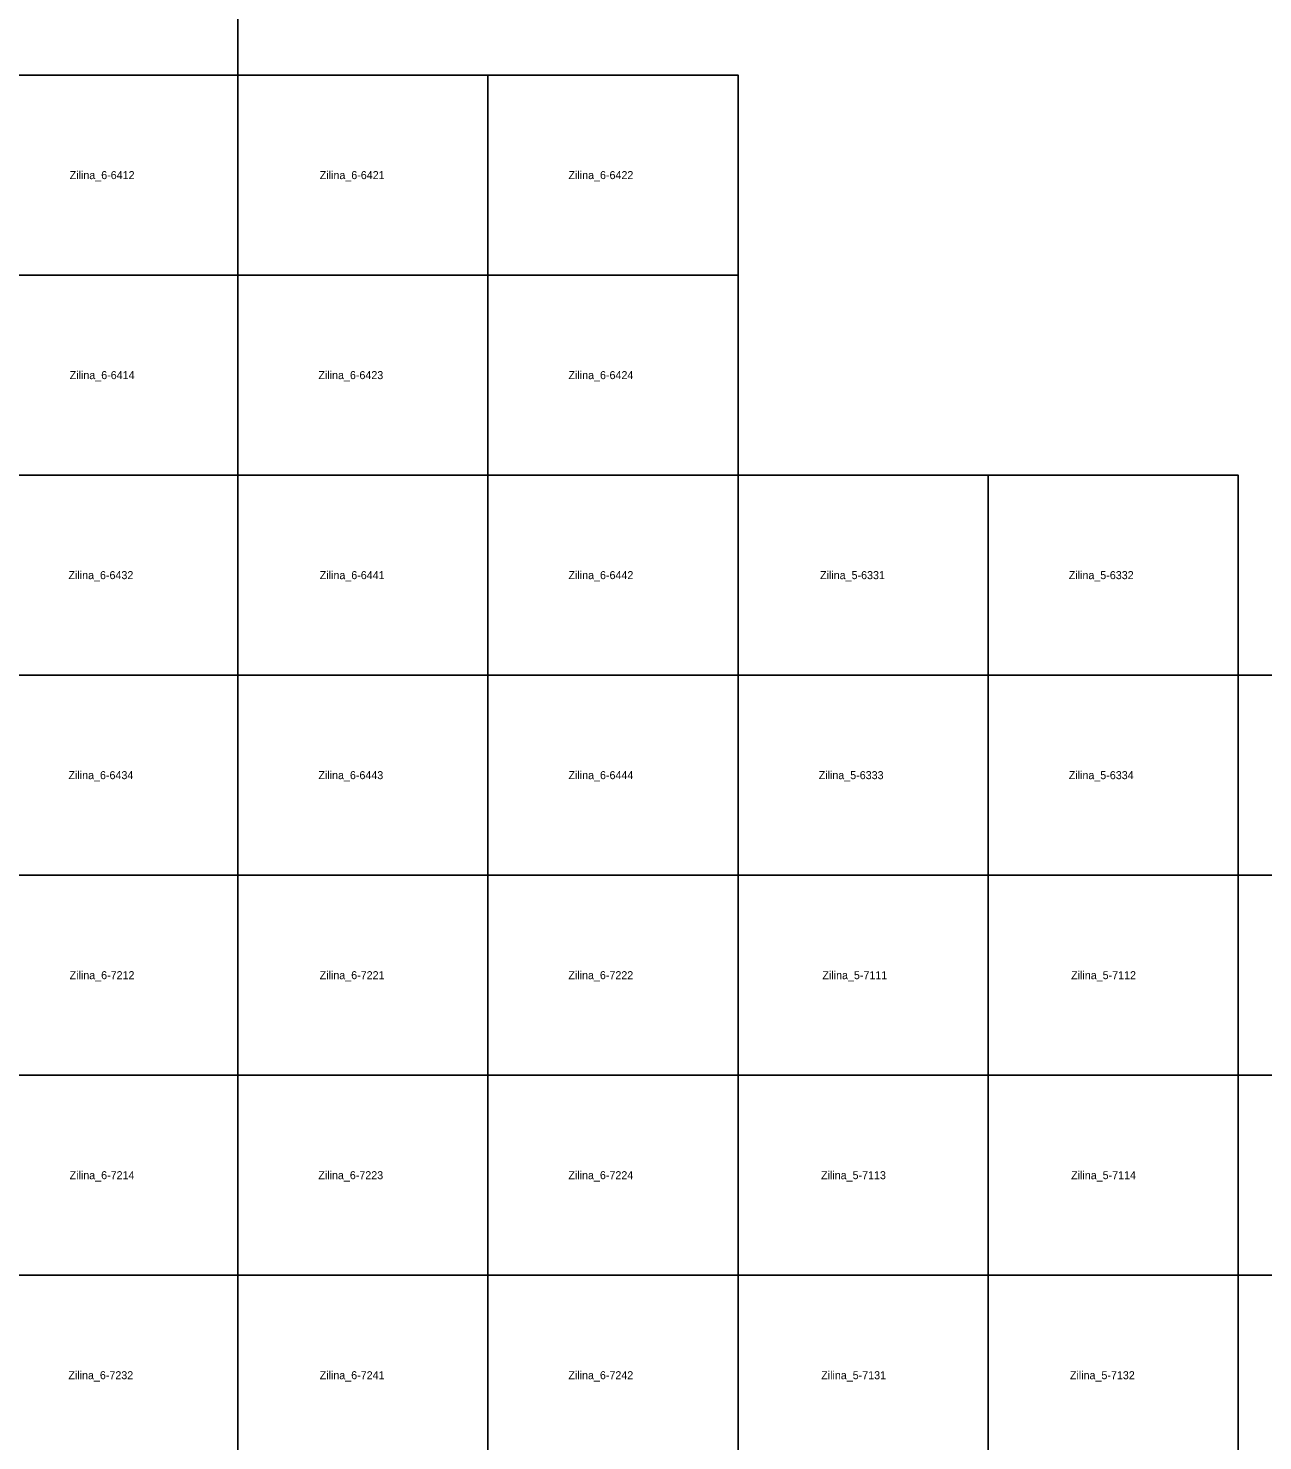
# Model space of a CAD drawing. Extents: x -445938 to -437812, y -1177250 to -1169500.
# Drawn here: x -440887 to -439344, y -1174707 to -1172941 of the extents above; entities that cross this region are included whole.
import ezdxf

# ---------------------------------------------------------------- set-up
doc = ezdxf.new("R2010")
doc.units = 0
for name, color, linetype in [('Vrstva 1', 7, 'Continuous'), ('Vrstva 4', 7, 'Continuous'), ('Vrstva 6', 7, 'Continuous')]:
    doc.layers.add(name, color=color, linetype=linetype)

msp = doc.modelspace()

# ---------------------------------------------------------------- linework, layer by layer
at = {"layer": 'Vrstva 1'}
msp.add_lwpolyline([(-440937.5, -1172000), (-440625, -1172000), (-440625, -1173000), (-440000, -1173000), (-440000, -1173500), (-439375, -1173500), (-439375, -1173750), (-438750, -1173750), (-438750, -1174000), (-438125, -1174000), (-438125, -1174750), (-437812.5, -1174750), (-437812.5, -1176750), (-438125, -1176750), (-438125, -1177000), (-438437.5, -1177000), (-438437.5, -1177250), (-439687.5, -1177250), (-439687.5, -1176750), (-440625, -1176750), (-440625, -1175500), (-441562.5, -1175500)], dxfattribs=at)
at = {"layer": 'Vrstva 4'}
for points in [[(-440625, -1172750), (-440625, -1173000), (-440937.5, -1173000), (-440937.5, -1172750)], [(-440625, -1173000), (-440625, -1173250), (-440937.5, -1173250), (-440937.5, -1173000)], [(-440312.5, -1173000), (-440312.5, -1173250), (-440625, -1173250), (-440625, -1173000)], [(-440000, -1173000), (-440000, -1173250), (-440312.5, -1173250), (-440312.5, -1173000)], [(-440625, -1173250), (-440625, -1173500), (-440937.5, -1173500), (-440937.5, -1173250)], [(-440312.5, -1173250), (-440312.5, -1173500), (-440625, -1173500), (-440625, -1173250)], [(-440000, -1173250), (-440000, -1173500), (-440312.5, -1173500), (-440312.5, -1173250)], [(-440625, -1173500), (-440625, -1173750), (-440937.5, -1173750), (-440937.5, -1173500)], [(-440312.5, -1173500), (-440312.5, -1173750), (-440625, -1173750), (-440625, -1173500)], [(-440000, -1173500), (-440000, -1173750), (-440312.5, -1173750), (-440312.5, -1173500)], [(-439687.5, -1173500), (-439687.5, -1173750), (-440000, -1173750), (-440000, -1173500)], [(-439375, -1173500), (-439375, -1173750), (-439687.5, -1173750), (-439687.5, -1173500)], [(-440625, -1173750), (-440625, -1174000), (-440937.5, -1174000), (-440937.5, -1173750)], [(-440312.5, -1173750), (-440312.5, -1174000), (-440625, -1174000), (-440625, -1173750)], [(-440000, -1173750), (-440000, -1174000), (-440312.5, -1174000), (-440312.5, -1173750)], [(-439687.5, -1173750), (-439687.5, -1174000), (-440000, -1174000), (-440000, -1173750)], [(-439375, -1173750), (-439375, -1174000), (-439687.5, -1174000), (-439687.5, -1173750)], [(-439062.5, -1173750), (-439062.5, -1174000), (-439375, -1174000), (-439375, -1173750)], [(-440625, -1174000), (-440625, -1174250), (-440937.5, -1174250), (-440937.5, -1174000)], [(-440312.5, -1174000), (-440312.5, -1174250), (-440625, -1174250), (-440625, -1174000)], [(-440000, -1174000), (-440000, -1174250), (-440312.5, -1174250), (-440312.5, -1174000)], [(-439687.5, -1174000), (-439687.5, -1174250), (-440000, -1174250), (-440000, -1174000)], [(-439375, -1174000), (-439375, -1174250), (-439687.5, -1174250), (-439687.5, -1174000)], [(-439062.5, -1174000), (-439062.5, -1174250), (-439375, -1174250), (-439375, -1174000)], [(-440625, -1174250), (-440625, -1174500), (-440937.5, -1174500), (-440937.5, -1174250)], [(-440312.5, -1174250), (-440312.5, -1174500), (-440625, -1174500), (-440625, -1174250)], [(-440000, -1174250), (-440000, -1174500), (-440312.5, -1174500), (-440312.5, -1174250)], [(-439687.5, -1174250), (-439687.5, -1174500), (-440000, -1174500), (-440000, -1174250)], [(-439375, -1174250), (-439375, -1174500), (-439687.5, -1174500), (-439687.5, -1174250)], [(-439062.5, -1174250), (-439062.5, -1174500), (-439375, -1174500), (-439375, -1174250)], [(-440625, -1174500), (-440625, -1174750), (-440937.5, -1174750), (-440937.5, -1174500)], [(-440312.5, -1174500), (-440312.5, -1174750), (-440625, -1174750), (-440625, -1174500)], [(-440000, -1174500), (-440000, -1174750), (-440312.5, -1174750), (-440312.5, -1174500)], [(-439687.5, -1174500), (-439687.5, -1174750), (-440000, -1174750), (-440000, -1174500)], [(-439375, -1174500), (-439375, -1174750), (-439687.5, -1174750), (-439687.5, -1174500)], [(-439062.5, -1174500), (-439062.5, -1174750), (-439375, -1174750), (-439375, -1174500)]]:
    msp.add_lwpolyline(points, close=True, dxfattribs=at)

# ---------------------------------------------------------------- texts
at = {"layer": 'Vrstva 6'}
for s, p in [('Zilina_6-6412', (-440835.144, -1173130)), ('Zilina_6-6421', (-440522.643, -1173130)), ('Zilina_6-6422', (-440211.836, -1173130)), ('Zilina_6-6414', (-440835.144, -1173380)), ('Zilina_6-6423', (-440524.336, -1173380)), ('Zilina_6-6424', (-440211.836, -1173380)), ('Zilina_6-6432', (-440836.678, -1173630)), ('Zilina_6-6441', (-440522.643, -1173630)), ('Zilina_6-6442', (-440211.836, -1173630)), ('Zilina_5-6331', (-439897.446, -1173630)), ('Zilina_5-6332', (-439586.638, -1173630)), ('Zilina_6-6434', (-440836.678, -1173880)), ('Zilina_6-6443', (-440524.336, -1173880)), ('Zilina_6-6444', (-440211.836, -1173880)), ('Zilina_5-6333', (-439899.138, -1173880)), ('Zilina_5-6334', (-439586.638, -1173880)), ('Zilina_6-7212', (-440835.261, -1174130)), ('Zilina_6-7221', (-440522.76, -1174130)), ('Zilina_6-7222', (-440211.954, -1174130)), ('Zilina_5-7111', (-439894.494, -1174130)), ('Zilina_5-7112', (-439583.686, -1174130)), ('Zilina_6-7214', (-440835.261, -1174380)), ('Zilina_6-7223', (-440524.454, -1174380)), ('Zilina_6-7224', (-440211.954, -1174380)), ('Zilina_5-7113', (-439896.186, -1174380)), ('Zilina_5-7114', (-439583.686, -1174380)), ('Zilina_6-7232', (-440836.796, -1174630)), ('Zilina_6-7241', (-440522.76, -1174630)), ('Zilina_6-7242', (-440211.954, -1174630)), ('Zilina_5-7131', (-439896.028, -1174630)), ('Zilina_5-7132', (-439585.222, -1174630))]:
    msp.add_text(s, height=10, dxfattribs=at).set_placement(p)

doc.saveas('drawing.dxf')
